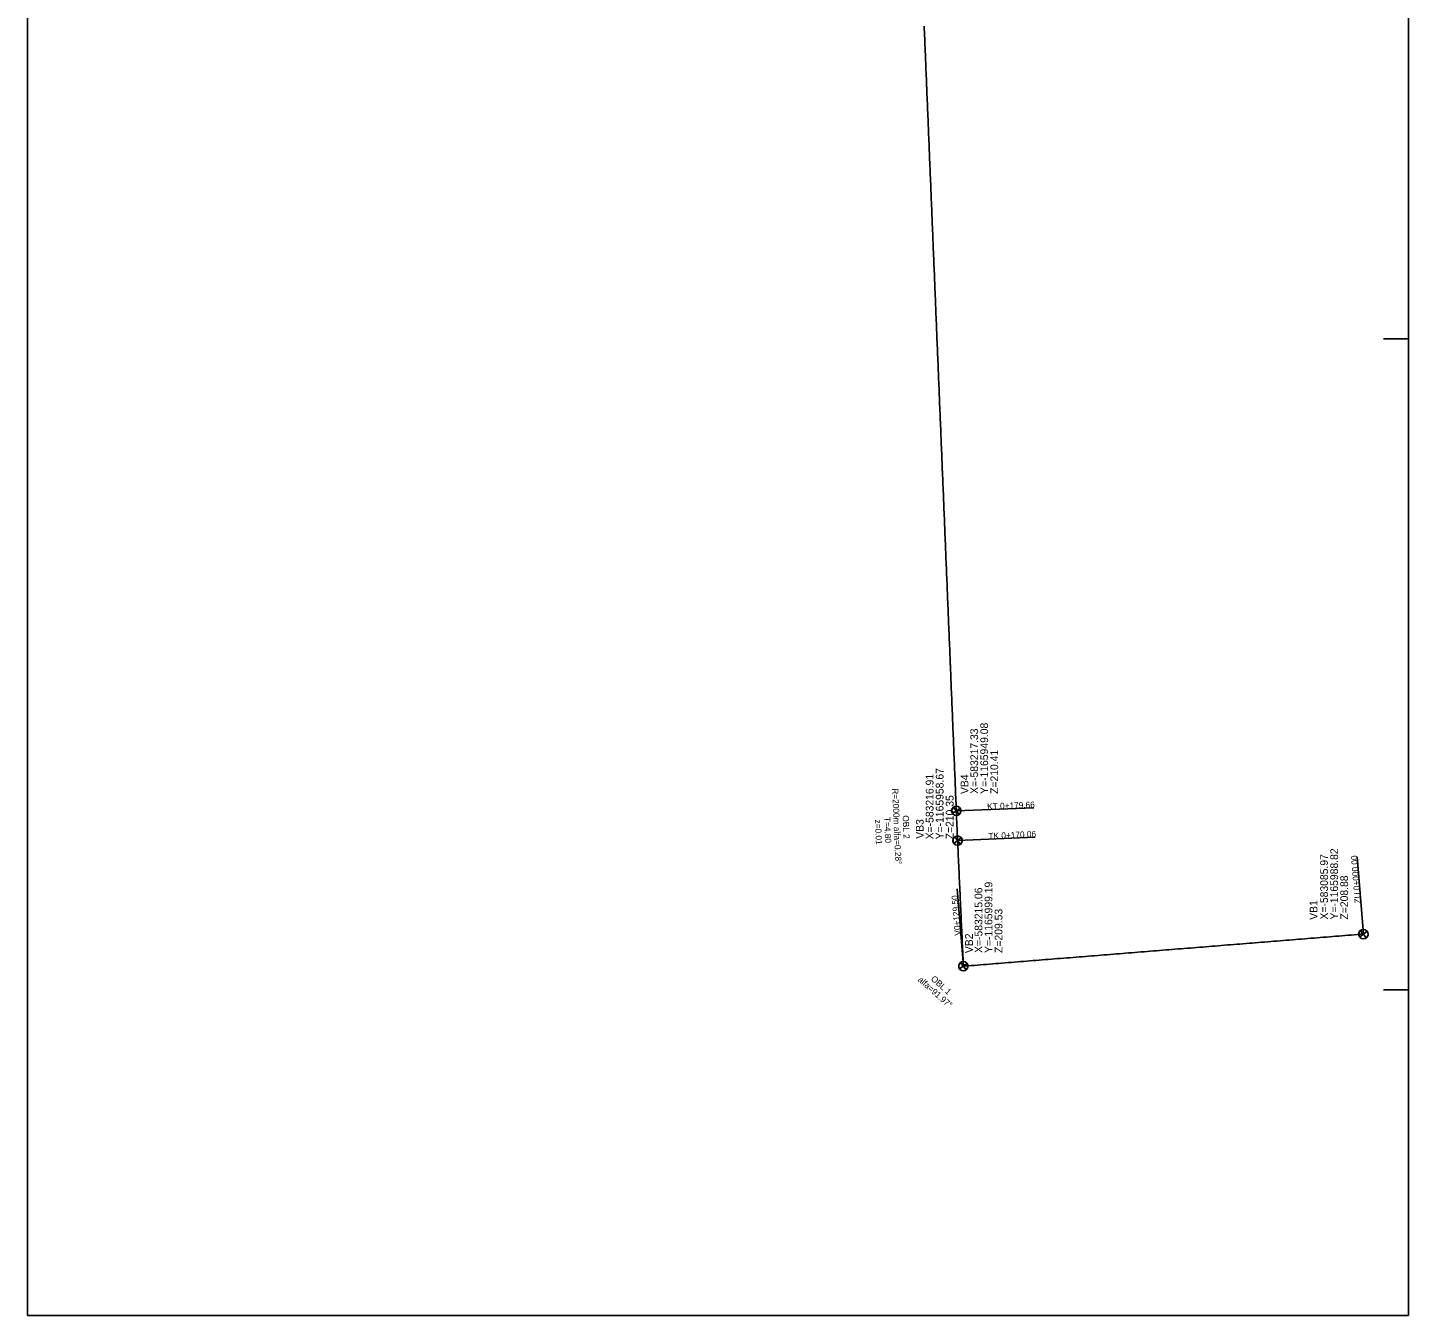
# Model space of a CAD drawing. Extents: x -583517 to -548566, y -1166112 to -1101582.
# Drawn here: x -583517 to -583071.5, y -1166111.8 to -1165696.4 of the extents above; entities that cross this region are included whole.
import ezdxf

# ---------------------------------------------------------------- set-up
doc = ezdxf.new("R2010")
doc.units = 0
for name, color, linetype in [('13', 7, 'Continuous'), ('59', 7, 'Continuous'), ('8', 7, 'Continuous'), ('Body pricny rez', 7, 'Continuous'), ('Popis pricneho profilu', 7, 'Continuous')]:
    doc.layers.add(name, color=color, linetype=linetype)

msp = doc.modelspace()

# ---------------------------------------------------------------- linework, layer by layer
at = {"layer": '13'}
for points in [[(-583217.33, -1165949.08), (-583192.35, -1165948.05)], [(-583216.91, -1165958.67), (-583191.94, -1165957.53)], [(-583085.97, -1165988.82), (-583087.98, -1165963.9)], [(-583215.06, -1165999.19), (-583217.06, -1165974.27)]]:
    msp.add_lwpolyline(points, dxfattribs=at)
at = {"layer": '8'}
for p, q in [((-583218.53, -1165949.97), (-583216.12, -1165948.18)), ((-583218.53, -1165949.97), (-583217.33, -1165949.08)), ((-583216.43, -1165950.28), (-583218.22, -1165947.87)), ((-583217.33, -1165949.08), (-583218.22, -1165947.87)), ((-583216.12, -1165948.18), (-583217.33, -1165949.08)), ((-583216.12, -1165948.18), (-583217.33, -1165949.08)), ((-583217.33, -1165949.08), (-583216.43, -1165950.28)), ((-583217.33, -1165949.08), (-583216.43, -1165950.28)), ((-583218.12, -1165959.56), (-583215.71, -1165957.77)), ((-583216.91, -1165958.67), (-583217.81, -1165957.46)), ((-583216.02, -1165959.87), (-583217.81, -1165957.47)), ((-583215.71, -1165957.77), (-583216.91, -1165958.67)), ((-583215.71, -1165957.77), (-583216.91, -1165958.67)), ((-583218.12, -1165959.56), (-583216.91, -1165958.67)), ((-583216.91, -1165958.67), (-583216.02, -1165959.87)), ((-583216.91, -1165958.67), (-583216.02, -1165959.87)), ((-583087.18, -1165989.72), (-583084.77, -1165987.93)), ((-583087.18, -1165989.72), (-583085.97, -1165988.82)), ((-583085.08, -1165990.03), (-583086.87, -1165987.62)), ((-583085.97, -1165988.82), (-583086.87, -1165987.62)), ((-583084.77, -1165987.93), (-583085.97, -1165988.82)), ((-583084.77, -1165987.93), (-583085.97, -1165988.82)), ((-583085.97, -1165988.82), (-583085.08, -1165990.03)), ((-583085.97, -1165988.82), (-583085.08, -1165990.03)), ((-583214.16, -1166000.39), (-583215.95, -1165997.98)), ((-583215.06, -1165999.19), (-583215.95, -1165997.98)), ((-583216.26, -1166000.08), (-583213.86, -1165998.29)), ((-583216.26, -1166000.08), (-583215.06, -1165999.19)), ((-583213.85, -1165998.29), (-583215.06, -1165999.19)), ((-583213.85, -1165998.29), (-583215.06, -1165999.19)), ((-583215.06, -1165999.19), (-583214.16, -1166000.39)), ((-583215.06, -1165999.19), (-583214.16, -1166000.39))]:
    msp.add_line(p, q, dxfattribs=at)
for centre in [(-583217.33, -1165949.08), (-583216.91, -1165958.67), (-583085.97, -1165988.82), (-583215.06, -1165999.19)]:
    msp.add_circle(centre, 1.5, dxfattribs=at)
for centre, start, end in [((-583217.33, -1165949.08), 126.6271, 216.6271), ((-583217.33, -1165949.08), 306.6271, 36.6271), ((-583217.33, -1165949.08), 306.6271, 36.6271), ((-583216.91, -1165958.67), 126.6271, 216.6271), ((-583216.91, -1165958.67), 306.6271, 36.6271), ((-583216.91, -1165958.67), 306.6271, 36.6271), ((-583085.97, -1165988.82), 126.6271, 216.6271), ((-583085.97, -1165988.82), 306.6271, 36.6271), ((-583085.97, -1165988.82), 306.6271, 36.6271), ((-583215.06, -1165999.19), 126.6271, 216.6271), ((-583215.06, -1165999.19), 306.6271, 36.6271), ((-583215.06, -1165999.19), 306.6271, 36.6271)]:
    msp.add_arc(centre, 1.5, start, end, dxfattribs=at)
at = {"layer": 'Body pricny rez'}
msp.add_lwpolyline([(-583085.97, -1165988.82), (-583086.97, -1165988.9), (-583087.97, -1165988.98), (-583088.96, -1165989.06), (-583089.96, -1165989.14), (-583090.96, -1165989.22), (-583091.96, -1165989.3), (-583092.95, -1165989.38), (-583093.95, -1165989.46), (-583094.95, -1165989.54), (-583095.94, -1165989.62), (-583096.94, -1165989.7), (-583097.94, -1165989.78), (-583098.93, -1165989.86), (-583099.93, -1165989.94), (-583100.93, -1165990.02), (-583101.92, -1165990.1), (-583102.92, -1165990.18), (-583103.92, -1165990.26), (-583104.91, -1165990.34), (-583105.91, -1165990.42), (-583106.91, -1165990.5), (-583107.9, -1165990.58), (-583108.9, -1165990.66), (-583109.9, -1165990.74), (-583110.89, -1165990.82), (-583111.89, -1165990.9), (-583112.89, -1165990.98), (-583113.88, -1165991.06), (-583114.88, -1165991.14), (-583115.88, -1165991.22), (-583116.87, -1165991.3), (-583117.87, -1165991.38), (-583118.87, -1165991.46), (-583119.87, -1165991.54), (-583120.86, -1165991.62), (-583121.86, -1165991.7), (-583122.86, -1165991.78), (-583123.85, -1165991.86), (-583124.85, -1165991.94), (-583125.85, -1165992.02), (-583126.84, -1165992.1), (-583127.84, -1165992.18), (-583128.84, -1165992.26), (-583129.83, -1165992.34), (-583130.83, -1165992.42), (-583131.83, -1165992.51), (-583132.82, -1165992.59), (-583133.82, -1165992.67), (-583134.82, -1165992.75), (-583135.81, -1165992.83), (-583136.81, -1165992.91), (-583137.81, -1165992.99), (-583138.8, -1165993.07), (-583139.8, -1165993.15), (-583140.8, -1165993.23), (-583141.79, -1165993.31), (-583142.79, -1165993.39), (-583143.79, -1165993.47), (-583144.78, -1165993.55), (-583145.78, -1165993.63), (-583146.78, -1165993.71), (-583147.78, -1165993.79), (-583148.77, -1165993.87), (-583149.77, -1165993.95), (-583150.77, -1165994.03), (-583151.76, -1165994.11), (-583152.76, -1165994.19), (-583153.76, -1165994.27), (-583154.75, -1165994.35), (-583155.75, -1165994.43), (-583156.75, -1165994.51), (-583157.74, -1165994.59), (-583158.74, -1165994.67), (-583159.74, -1165994.75), (-583160.73, -1165994.83), (-583161.73, -1165994.91), (-583162.73, -1165994.99), (-583163.72, -1165995.07), (-583164.72, -1165995.15), (-583165.72, -1165995.23), (-583166.71, -1165995.31), (-583167.71, -1165995.39), (-583168.71, -1165995.47), (-583169.7, -1165995.55), (-583170.7, -1165995.63), (-583171.7, -1165995.71), (-583172.7, -1165995.79), (-583173.69, -1165995.87), (-583174.69, -1165995.95), (-583175.69, -1165996.03), (-583176.68, -1165996.11), (-583177.68, -1165996.19), (-583178.68, -1165996.27), (-583179.67, -1165996.35), (-583180.67, -1165996.43), (-583181.67, -1165996.51), (-583182.66, -1165996.59), (-583183.66, -1165996.67), (-583184.66, -1165996.75), (-583185.65, -1165996.83), (-583186.65, -1165996.91), (-583187.65, -1165996.99), (-583188.64, -1165997.07), (-583189.64, -1165997.15), (-583190.64, -1165997.23), (-583191.63, -1165997.31), (-583192.63, -1165997.39), (-583193.63, -1165997.47), (-583194.62, -1165997.55), (-583195.62, -1165997.63), (-583196.62, -1165997.71), (-583197.61, -1165997.79), (-583198.61, -1165997.87), (-583199.61, -1165997.95), (-583200.61, -1165998.03), (-583201.6, -1165998.11), (-583202.6, -1165998.19), (-583203.6, -1165998.27), (-583204.59, -1165998.35), (-583205.59, -1165998.43), (-583206.59, -1165998.51), (-583207.58, -1165998.59), (-583208.58, -1165998.67), (-583209.58, -1165998.75), (-583210.57, -1165998.83), (-583211.57, -1165998.91), (-583212.57, -1165998.99), (-583213.56, -1165999.07), (-583214.56, -1165999.15), (-583215.06, -1165999.19), (-583215.08, -1165998.69), (-583215.13, -1165997.7), (-583215.13, -1165997.7), (-583215.13, -1165997.69), (-583215.17, -1165996.69), (-583215.22, -1165995.69), (-583215.26, -1165994.69), (-583215.31, -1165993.69), (-583215.36, -1165992.7), (-583215.4, -1165991.7), (-583215.45, -1165990.7), (-583215.49, -1165989.7), (-583215.54, -1165988.7), (-583215.58, -1165987.7), (-583215.63, -1165986.7), (-583215.68, -1165985.7), (-583215.72, -1165984.7), (-583215.77, -1165983.7), (-583215.81, -1165982.71), (-583215.86, -1165981.71), (-583215.9, -1165980.71), (-583215.95, -1165979.71), (-583216, -1165978.71), (-583216.04, -1165977.71), (-583216.09, -1165976.71), (-583216.13, -1165975.71), (-583216.18, -1165974.71), (-583216.22, -1165973.71), (-583216.27, -1165972.72), (-583216.32, -1165971.72), (-583216.36, -1165970.72), (-583216.41, -1165969.72), (-583216.45, -1165968.72), (-583216.5, -1165967.72), (-583216.54, -1165966.72), (-583216.59, -1165965.72), (-583216.64, -1165964.72), (-583216.68, -1165963.73), (-583216.73, -1165962.73), (-583216.77, -1165961.73), (-583216.82, -1165960.73), (-583216.86, -1165959.73), (-583216.91, -1165958.73), (-583216.91, -1165958.67), (-583216.96, -1165957.73), (-583217, -1165956.73), (-583217.04, -1165955.73), (-583217.09, -1165954.73), (-583217.13, -1165953.74), (-583217.18, -1165952.74), (-583217.22, -1165951.74), (-583217.26, -1165950.74), (-583217.3, -1165949.74), (-583217.33, -1165949.08), (-583217.34, -1165948.74), (-583217.38, -1165947.74), (-583217.42, -1165946.74), (-583217.46, -1165945.74), (-583217.51, -1165944.74), (-583217.55, -1165943.74), (-583217.59, -1165942.74), (-583217.63, -1165941.75), (-583217.67, -1165940.75), (-583217.71, -1165939.75), (-583217.75, -1165938.75), (-583217.79, -1165937.75), (-583217.83, -1165936.75), (-583217.87, -1165935.75), (-583217.9, -1165935.04), (-583217.91, -1165934.75), (-583217.96, -1165933.75), (-583218, -1165932.75), (-583218.04, -1165931.75), (-583218.08, -1165930.75), (-583218.12, -1165929.76), (-583218.16, -1165928.76), (-583218.19, -1165927.91), (-583218.2, -1165927.76), (-583218.24, -1165926.76), (-583218.26, -1165926.25), (-583218.28, -1165925.76), (-583218.32, -1165924.76), (-583218.36, -1165923.76), (-583218.41, -1165922.76), (-583218.45, -1165921.76), (-583218.49, -1165920.76), (-583218.53, -1165919.76), (-583218.57, -1165918.77), (-583218.61, -1165917.77), (-583218.65, -1165916.77), (-583218.69, -1165915.77), (-583218.73, -1165914.77), (-583218.77, -1165913.77), (-583218.81, -1165912.77), (-583218.86, -1165911.77), (-583218.9, -1165910.77), (-583218.94, -1165909.77), (-583218.95, -1165909.54), (-583218.98, -1165908.77), (-583219.02, -1165907.77), (-583219.06, -1165906.78), (-583219.1, -1165905.78), (-583219.11, -1165905.51), (-583219.14, -1165904.78), (-583219.14, -1165904.75), (-583219.15, -1165904.63), (-583219.18, -1165903.78), (-583219.22, -1165902.78), (-583219.25, -1165902.03), (-583219.26, -1165901.78), (-583219.31, -1165900.78), (-583219.35, -1165899.78), (-583219.39, -1165898.78), (-583219.43, -1165897.78), (-583219.47, -1165896.78), (-583219.51, -1165895.78), (-583219.55, -1165894.79), (-583219.59, -1165893.79), (-583219.63, -1165892.79), (-583219.67, -1165891.79), (-583219.71, -1165890.79), (-583219.76, -1165889.79), (-583219.8, -1165888.79), (-583219.84, -1165887.79), (-583219.88, -1165886.79), (-583219.92, -1165885.79), (-583219.96, -1165884.79), (-583220, -1165883.79), (-583220.04, -1165882.8), (-583220.08, -1165881.8), (-583220.12, -1165880.8), (-583220.16, -1165879.8), (-583220.21, -1165878.8), (-583220.25, -1165877.8), (-583220.29, -1165876.8), (-583220.33, -1165875.8), (-583220.37, -1165874.8), (-583220.41, -1165873.8), (-583220.45, -1165872.8), (-583220.49, -1165871.8), (-583220.53, -1165870.81), (-583220.57, -1165869.81), (-583220.61, -1165868.81), (-583220.66, -1165867.81), (-583220.7, -1165866.81), (-583220.74, -1165865.81), (-583220.78, -1165864.81), (-583220.82, -1165863.81), (-583220.86, -1165862.81), (-583220.9, -1165861.81), (-583220.94, -1165860.81), (-583220.98, -1165859.81), (-583221.02, -1165858.82), (-583221.03, -1165858.57), (-583221.06, -1165857.82), (-583221.11, -1165856.82), (-583221.15, -1165855.82), (-583221.18, -1165854.88), (-583221.19, -1165854.82), (-583221.23, -1165853.82), (-583221.27, -1165852.82), (-583221.31, -1165851.82), (-583221.35, -1165850.82), (-583221.39, -1165849.82), (-583221.43, -1165848.82), (-583221.47, -1165847.82), (-583221.51, -1165846.83), (-583221.56, -1165845.83), (-583221.6, -1165844.83), (-583221.64, -1165843.83), (-583221.68, -1165842.83), (-583221.72, -1165841.83), (-583221.76, -1165840.83), (-583221.8, -1165839.83), (-583221.84, -1165838.83), (-583221.88, -1165837.83), (-583221.92, -1165836.83), (-583221.96, -1165835.83), (-583221.98, -1165835.49), (-583222.01, -1165834.84), (-583222.05, -1165833.84), (-583222.09, -1165832.84), (-583222.13, -1165831.84), (-583222.17, -1165830.84), (-583222.21, -1165829.84), (-583222.25, -1165828.84), (-583222.29, -1165827.99), (-583222.29, -1165827.84), (-583222.33, -1165826.84), (-583222.37, -1165825.84), (-583222.41, -1165824.84), (-583222.46, -1165823.84), (-583222.5, -1165822.85), (-583222.54, -1165821.85), (-583222.58, -1165820.85), (-583222.62, -1165819.85), (-583222.66, -1165818.85), (-583222.7, -1165817.85), (-583222.74, -1165816.85), (-583222.78, -1165815.85), (-583222.82, -1165814.85), (-583222.86, -1165813.85), (-583222.9, -1165812.85), (-583222.95, -1165811.85), (-583222.99, -1165810.86), (-583223.03, -1165809.86), (-583223.07, -1165808.86), (-583223.11, -1165807.86), (-583223.15, -1165806.86), (-583223.19, -1165805.86), (-583223.23, -1165804.86), (-583223.27, -1165803.86), (-583223.31, -1165802.86), (-583223.35, -1165801.86), (-583223.4, -1165800.86), (-583223.44, -1165799.86), (-583223.48, -1165798.87), (-583223.51, -1165798.19), (-583223.52, -1165797.87), (-583223.56, -1165796.87), (-583223.59, -1165796.19), (-583223.6, -1165795.96), (-583223.6, -1165795.87), (-583223.64, -1165794.87), (-583223.68, -1165793.87), (-583223.72, -1165792.87), (-583223.76, -1165791.87), (-583223.8, -1165790.87), (-583223.85, -1165789.87), (-583223.89, -1165788.87), (-583223.93, -1165787.87), (-583223.97, -1165786.88), (-583224.01, -1165785.88), (-583224.05, -1165784.88), (-583224.09, -1165783.88), (-583224.13, -1165782.88), (-583224.17, -1165781.88), (-583224.21, -1165780.88), (-583224.25, -1165779.88), (-583224.3, -1165778.88), (-583224.34, -1165777.88), (-583224.38, -1165776.88), (-583224.42, -1165775.88), (-583224.46, -1165774.89), (-583224.5, -1165773.89), (-583224.54, -1165772.89), (-583224.56, -1165772.44), (-583224.58, -1165771.89), (-583224.62, -1165770.89), (-583224.66, -1165769.89), (-583224.7, -1165768.89), (-583224.75, -1165767.89), (-583224.79, -1165766.89), (-583224.82, -1165766.08), (-583224.83, -1165765.89), (-583224.87, -1165764.89), (-583224.91, -1165763.89), (-583224.95, -1165762.9), (-583224.99, -1165761.9), (-583225.03, -1165760.9), (-583225.07, -1165759.9), (-583225.11, -1165758.9), (-583225.15, -1165758.05), (-583225.15, -1165757.9), (-583225.16, -1165757.87), (-583225.2, -1165756.9), (-583225.24, -1165755.9), (-583225.28, -1165754.9), (-583225.32, -1165753.9), (-583225.36, -1165752.9), (-583225.4, -1165751.9), (-583225.44, -1165750.91), (-583225.48, -1165749.91), (-583225.52, -1165748.91), (-583225.56, -1165747.91), (-583225.6, -1165746.91), (-583225.65, -1165745.91), (-583225.69, -1165744.91), (-583225.73, -1165743.91), (-583225.77, -1165742.91), (-583225.81, -1165741.91), (-583225.85, -1165740.91), (-583225.89, -1165739.91), (-583225.93, -1165738.92), (-583225.97, -1165737.92), (-583226.01, -1165736.92), (-583226.05, -1165735.92), (-583226.1, -1165734.92), (-583226.14, -1165733.92), (-583226.18, -1165732.92), (-583226.22, -1165731.92), (-583226.26, -1165730.92), (-583226.26, -1165730.84), (-583226.3, -1165729.92), (-583226.33, -1165729.27), (-583226.34, -1165728.92), (-583226.38, -1165727.92), (-583226.42, -1165726.93), (-583226.46, -1165725.93), (-583226.5, -1165724.93), (-583226.55, -1165723.93), (-583226.59, -1165722.93), (-583226.63, -1165721.93), (-583226.67, -1165720.93), (-583226.71, -1165719.93), (-583226.75, -1165718.93), (-583226.79, -1165717.93), (-583226.79, -1165717.85), (-583226.83, -1165716.93), (-583226.87, -1165715.93), (-583226.91, -1165714.94), (-583226.95, -1165713.94), (-583227, -1165712.94), (-583227.04, -1165711.94), (-583227.08, -1165710.94), (-583227.12, -1165709.94), (-583227.16, -1165708.94), (-583227.2, -1165707.94), (-583227.24, -1165706.94), (-583227.28, -1165705.94), (-583227.32, -1165704.94), (-583227.35, -1165704.26), (-583227.36, -1165703.94), (-583227.38, -1165703.54), (-583227.38, -1165703.44), (-583227.4, -1165703.15), (-583227.4, -1165702.95), (-583227.45, -1165701.95), (-583227.49, -1165700.95), (-583227.53, -1165699.95), (-583227.57, -1165698.95), (-583227.61, -1165697.95), (-583227.65, -1165696.95), (-583227.69, -1165695.95)], dxfattribs=at)
at = {"layer": 'Popis pricneho profilu'}
for p, q in [((-583071.47, -1165796.82), (-583079.47, -1165796.82)), ((-583071.47, -1166006.82), (-583079.47, -1166006.82))]:
    msp.add_line(p, q, dxfattribs=at)
msp.add_lwpolyline([(-583516.97, -1166111.82), (-583516.97, -1165166.82), (-583071.47, -1165166.82), (-583071.47, -1166111.82)], close=True, dxfattribs=at)

# ---------------------------------------------------------------- texts
at = {"layer": '13'}
for s, rotation, p in [('R=2000m alfa=0.28%%d', 272.4818, (-583238.04, -1165941.84)), ('KT 0+179.66', 2.3443, (-583207.34, -1165948.67)), ('   z=0.01', 272.4818, (-583243.71, -1165949.69)), ('  T=4.80', 272.4818, (-583240.71, -1165949.6)), ('OBL 2', 272.4818, (-583234.66, -1165950.55)), ('TK 0+170.06', 2.6193, (-583206.92, -1165958.21)), ('ZU 0+000.00', 94.5908, (-583086.77, -1165978.86)), ('V0+129.50', 94.5908, (-583215.86, -1165989.22)), ('OBL 1', 318.6051, (-583225.71, -1166003.53)), (' alfa=91.97%%d', 318.6051, (-583230.48, -1166003.32))]:
    msp.add_text(s, height=2, rotation=rotation, dxfattribs=at).set_placement(p)
at = {"layer": '59'}
for s, p in [('Y=-1165949.08', (-583207.07, -1165943.6)), ('X=-583217.33', (-583210.3, -1165943.6)), ('Z=210.41', (-583203.83, -1165943.6)), ('Y=-1165958.67', (-583221.45, -1165958.25)), ('X=-583216.91', (-583224.69, -1165958.25)), ('VB4', (-583213.43, -1165943.64)), ('Z=210.35', (-583218.22, -1165958.25)), ('VB3', (-583227.86, -1165958.05)), ('Y=-1165988.82', (-583094.17, -1165984.13)), ('X=-583085.97', (-583097.41, -1165984.13)), ('Z=208.88', (-583090.93, -1165984.13)), ('X=-583215.06', (-583208.92, -1165994.9)), ('Y=-1165999.19', (-583205.69, -1165994.9)), ('VB1', (-583100.82, -1165984.22)), ('Z=209.53', (-583202.45, -1165994.9)), ('VB2', (-583211.99, -1165994.96))]:
    msp.add_text(s, height=2.5, rotation=90, dxfattribs=at).set_placement(p)

doc.saveas('drawing.dxf')
